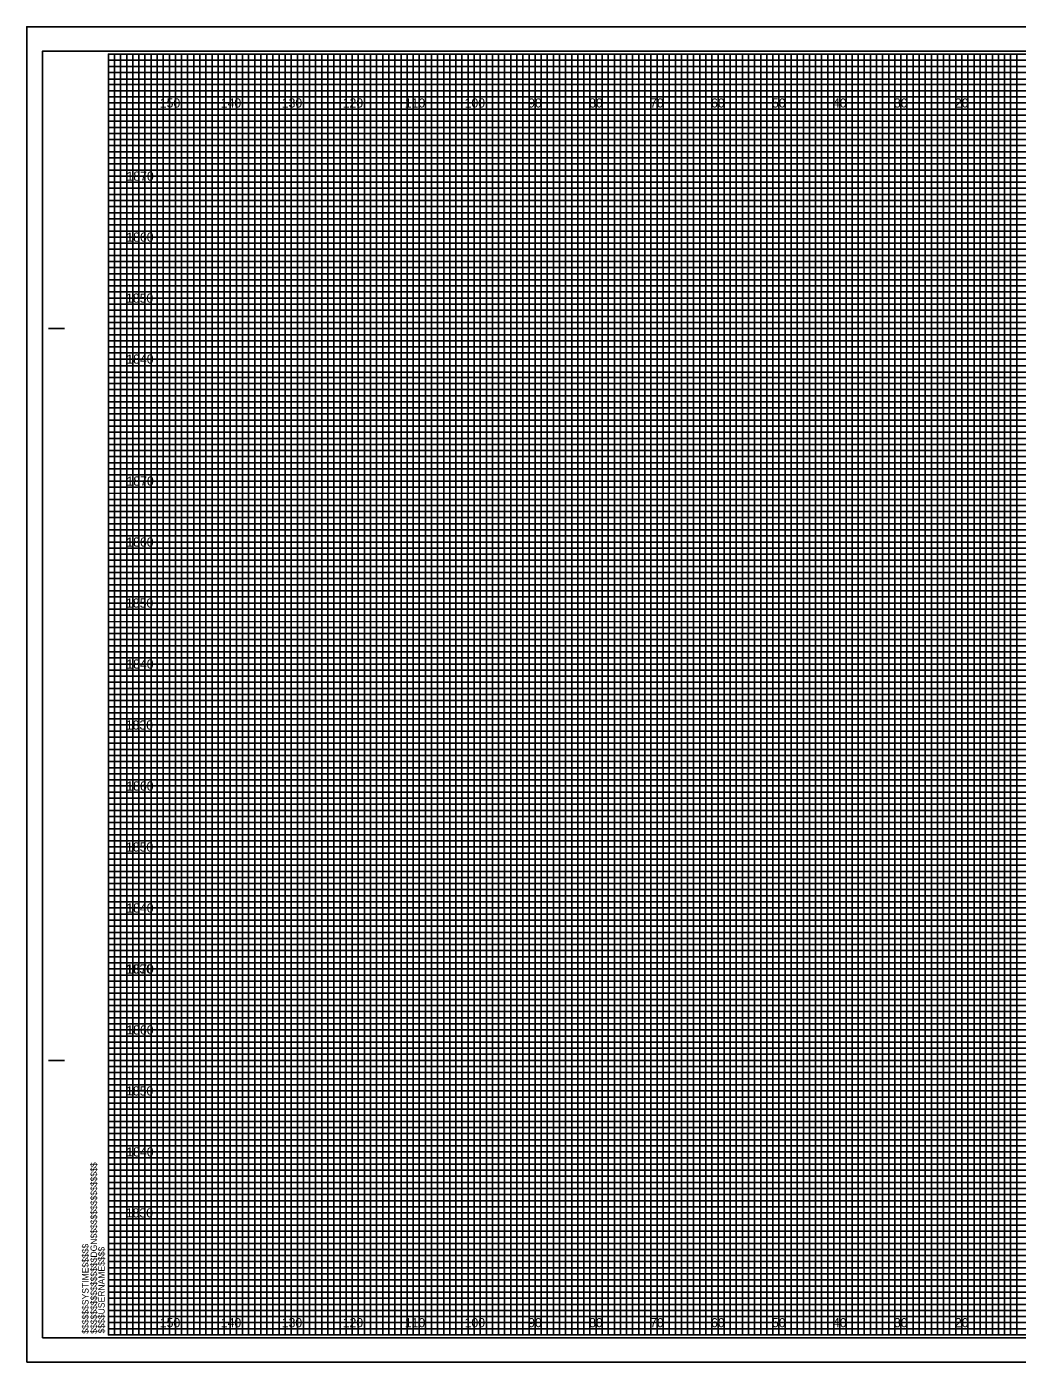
# Model space of a CAD drawing. Extents: x -13 to 323, y 8136 to 8354.
# Drawn here: x -13.4 to 149.1, y 8135.5 to 8354.5 of the extents above; entities that cross this region are included whole.
import ezdxf

# ---------------------------------------------------------------- set-up
doc = ezdxf.new("R2010")
doc.units = 0
for name, color, linetype in [('Prop XS Elevation Labels', 7, 'Continuous'), ('Prop XS Offset Labels', 7, 'Continuous'), ('Sheet Cross Section CELL', 7, 'Continuous'), ('Sheet Cross Section Grid Major CELL', 7, 'Continuous'), ('Sheet Cross Section Grid Middle CELL', 7, 'Continuous'), ('Sheet Cross Section Grid Minor 1 CELL', 7, 'Continuous'), ('Sheet Cross Section Grid Minor 2 CELL', 7, 'Continuous'), ('Sheet Cutting Line CELL', 7, 'Continuous'), ('Sheet DOT Grid CELL', 7, 'Continuous'), ('Sheet Plot Border Inside CELL', 7, 'Continuous'), ('Sheet Plot Border Outside CELL', 7, 'Continuous')]:
    doc.layers.add(name, color=color, linetype=linetype)

msp = doc.modelspace()

# ---------------------------------------------------------------- linework, layer by layer
at = {"layer": 'Sheet Cross Section CELL'}
for p, q in [((-9.8, 8305), (-7.3, 8305)), ((-9.7, 8305), (-7.2, 8305)), ((-9.8, 8185), (-7.3, 8185)), ((-9.7, 8185), (-7.2, 8185))]:
    msp.add_line(p, q, dxfattribs=at)
msp.add_lwpolyline([(320, 8350), (0, 8350), (0, 8140), (320, 8140)], close=True, dxfattribs=at)
at = {"layer": 'Sheet Cross Section Grid Major CELL'}
for p, q in [((10, 8350), (0, 8350)), ((10, 8140), (10, 8350)), ((30, 8350), (20, 8350)), ((20, 8350), (20, 8140)), ((30, 8140), (30, 8350)), ((50, 8350), (40, 8350)), ((40, 8350), (40, 8140)), ((50, 8140), (50, 8350)), ((70, 8350), (60, 8350)), ((60, 8350), (60, 8140)), ((70, 8140), (70, 8350)), ((90, 8350), (80, 8350)), ((80, 8350), (80, 8140)), ((90, 8140), (90, 8350)), ((110, 8350), (100, 8350)), ((100, 8350), (100, 8140)), ((110, 8140), (110, 8350)), ((130, 8350), (120, 8350)), ((120, 8350), (120, 8140)), ((130, 8140), (130, 8350)), ((150, 8350), (140, 8350)), ((140, 8350), (140, 8140)), ((20, 8140), (10, 8140)), ((40, 8140), (30, 8140)), ((60, 8140), (50, 8140)), ((80, 8140), (70, 8140)), ((100, 8140), (90, 8140)), ((120, 8140), (110, 8140)), ((140, 8140), (130, 8140))]:
    msp.add_line(p, q, dxfattribs=at)
for points in [[(0, 8340), (320, 8340), (320, 8330), (0, 8330)], [(0, 8320), (320, 8320), (320, 8310), (0, 8310)], [(0, 8300), (320, 8300), (320, 8290), (0, 8290)], [(0, 8280), (320, 8280), (320, 8270), (0, 8270)], [(0, 8260), (320, 8260), (320, 8250), (0, 8250)], [(0, 8240), (320, 8240), (320, 8230), (0, 8230)], [(0, 8220), (320, 8220), (320, 8210), (0, 8210)], [(0, 8200), (320, 8200), (320, 8190), (0, 8190)], [(0, 8180), (320, 8180), (320, 8170), (0, 8170)], [(0, 8160), (320, 8160), (320, 8150), (0, 8150)]]:
    msp.add_lwpolyline(points, dxfattribs=at)
at = {"layer": 'Sheet Cross Section Grid Middle CELL'}
for points in [[(0, 8350), (5, 8350), (5, 8140), (15, 8140), (15, 8350), (25, 8350), (25, 8140), (35, 8140), (35, 8350), (45, 8350), (45, 8140), (55, 8140), (55, 8350), (65, 8350), (65, 8140), (75, 8140), (75, 8350), (85, 8350), (85, 8140), (95, 8140), (95, 8350), (105, 8350), (105, 8140), (115, 8140), (115, 8350), (125, 8350), (125, 8140), (135, 8140), (135, 8350), (145, 8350), (145, 8140), (155, 8140)], [(0, 8345), (275, 8345)], [(0, 8325), (320, 8325), (320, 8335), (0, 8335)], [(0, 8305), (320, 8305), (320, 8315), (0, 8315)], [(0, 8285), (320, 8285), (320, 8295), (0, 8295)], [(0, 8265), (320, 8265), (320, 8275), (0, 8275)], [(0, 8245), (320, 8245), (320, 8255), (0, 8255)], [(0, 8225), (320, 8225), (320, 8235), (0, 8235)], [(0, 8205), (320, 8205), (320, 8215), (0, 8215)], [(0, 8185), (320, 8185), (320, 8195), (0, 8195)], [(0, 8165), (320, 8165), (320, 8175), (0, 8175)], [(0, 8145), (320, 8145), (320, 8155), (0, 8155)]]:
    msp.add_lwpolyline(points, dxfattribs=at)
at = {"layer": 'Sheet Cross Section Grid Minor 1 CELL'}
for p, q in [((0, 8349), (260, 8349)), ((260, 8347.98), (0, 8347.98)), ((0, 8347.98), (0, 8347)), ((0, 8347), (260, 8347)), ((260, 8345.89), (0, 8345.89)), ((0, 8345.89), (0, 8344)), ((0, 8344), (320, 8344))]:
    msp.add_line(p, q, dxfattribs=at)
for points in [[(0, 8343), (270, 8343), (320, 8343), (320, 8342), (0, 8342)], [(0, 8341), (320, 8341), (320, 8339), (0, 8339)], [(0, 8338), (320, 8338), (320, 8337), (0, 8336.98)], [(0, 8336), (320, 8336), (320, 8334), (0, 8334)], [(0, 8333), (320, 8333), (320, 8332), (0, 8332)], [(0, 8331), (320, 8331), (320, 8329), (0, 8329)], [(0, 8328), (320, 8328), (320, 8327), (0, 8327)], [(0, 8326), (320, 8326), (320, 8324), (0, 8324)], [(0, 8323), (320, 8323), (320, 8322), (0, 8322)], [(0, 8321), (320, 8321), (320, 8319), (0, 8319)], [(0, 8318), (320, 8318), (320, 8317), (0, 8317)], [(0, 8316), (320, 8316), (320, 8313.95), (320, 8313), (320, 8312), (0, 8312)], [(0, 8314), (320, 8314), (320, 8313), (0, 8313)], [(0, 8311), (320, 8311), (320, 8309), (0, 8309.03)], [(0, 8309.03), (320, 8309), (320, 8308), (0, 8308)], [(0, 8307), (320, 8307), (320, 8306), (0, 8306)], [(0, 8304), (320, 8304), (320, 8303), (0, 8303)], [(0, 8302), (320, 8302), (320, 8301), (0, 8301)], [(-0.07, 8298.89), (320, 8298.89), (320, 8297.88), (-0.07, 8297.88)], [(0, 8297), (320, 8297), (320, 8296), (0, 8296)], [(0, 8294), (320, 8294), (320, 8293), (0, 8293)], [(0, 8292), (320, 8292), (320, 8291), (0, 8291)], [(0, 8289), (320, 8289), (320, 8288), (0, 8288)], [(0, 8287), (320, 8287), (320, 8286), (0, 8286)], [(0, 8284), (320, 8284), (320, 8283), (0, 8283)], [(0, 8282), (320, 8282), (320, 8281), (0, 8281)], [(0, 8279), (320, 8279), (319.99, 8277.98), (0, 8278)], [(0, 8277), (320, 8277), (320, 8276), (0, 8276)], [(0, 8274), (320, 8274), (320, 8273), (0, 8273)], [(0, 8272), (320, 8272), (320, 8271), (0, 8271)], [(0, 8269), (320, 8269), (320, 8268), (0, 8268)], [(0, 8267), (320, 8267), (320, 8266), (0, 8266)], [(0, 8264), (320, 8264), (320, 8263), (0, 8263)], [(0, 8262), (320, 8262), (320, 8261), (0, 8261)], [(0, 8259), (320, 8259), (320, 8258), (0, 8258)], [(0, 8256.99), (320.07, 8256.91), (320, 8256), (0, 8256)], [(0, 8254), (320, 8254), (320, 8253), (0, 8253)], [(0, 8252), (320, 8252), (320, 8251), (0, 8251)], [(0, 8249), (320, 8249), (320, 8248), (0, 8248)], [(0, 8247), (320, 8247), (320, 8246), (0, 8246)], [(0, 8244), (320, 8244), (320, 8243), (0, 8243)], [(0, 8242), (320, 8242), (320, 8241), (0, 8241)], [(0, 8239), (320, 8239), (320, 8238), (0, 8238)], [(0, 8237), (320, 8237), (320, 8236), (0, 8236)], [(0, 8234), (320, 8234), (320, 8233), (0, 8233)], [(0, 8232), (320, 8232), (320, 8231), (0, 8231)], [(0, 8229), (320, 8229), (320, 8228), (0, 8228)], [(0, 8227), (320, 8227), (320, 8226), (0, 8226)], [(0, 8224), (320, 8224), (320, 8223), (0, 8223)], [(0, 8222), (320, 8222), (320, 8221), (0, 8221)], [(0, 8219), (320, 8219), (319.99, 8217.98), (0, 8218)], [(0, 8217), (320, 8217), (320, 8216), (0, 8216)], [(0, 8214), (320, 8214), (320, 8213), (0, 8213)], [(0, 8212), (320, 8212), (320, 8211), (0, 8211)], [(0, 8209), (320, 8209), (320, 8208), (0, 8208)], [(0, 8207), (320, 8207), (320, 8206), (0, 8206)], [(0, 8204), (320, 8204), (320, 8203), (0, 8203)], [(0, 8202), (320, 8202), (320, 8201), (0, 8201)], [(0, 8199), (320, 8199), (320, 8198), (0, 8198)], [(0, 8196.99), (320.07, 8196.91), (320, 8196), (0, 8196)], [(0, 8194), (320, 8194), (320, 8193), (0, 8193)], [(0, 8192), (320, 8192), (320, 8191), (0, 8191)], [(0, 8189), (320, 8189), (320, 8188), (0, 8188)], [(0, 8187), (320, 8187), (320, 8186), (0, 8186)], [(0, 8184), (320, 8184), (320, 8183), (0, 8183)], [(0, 8182), (320, 8182), (320, 8181), (0, 8181)], [(0, 8179), (320, 8179), (320, 8178), (0, 8178)], [(0, 8177), (320, 8177), (320, 8176), (0, 8176)], [(0, 8174), (320, 8174), (320, 8173), (0, 8173)], [(0, 8172), (320, 8172), (320, 8171), (0, 8171)], [(0, 8169), (320, 8169), (320, 8168), (0, 8168)], [(0, 8167), (320, 8167), (320, 8166), (0, 8166)], [(0, 8164), (320, 8164), (320, 8163), (0, 8163)], [(0, 8162), (320, 8162), (320, 8161), (0, 8161)], [(0, 8159), (320, 8159), (320, 8158), (0, 8158)], [(0, 8157), (320, 8157), (320, 8156), (0, 8156)], [(0, 8154), (320, 8154), (320, 8153), (0, 8153)], [(0, 8152), (320, 8152), (320, 8151), (0, 8151)], [(0, 8149), (320, 8149), (320, 8148), (0, 8148)], [(0, 8147), (320, 8147), (320, 8146), (0, 8146)], [(0, 8144), (320, 8144), (320, 8143), (0, 8143)], [(0, 8142), (320, 8142), (320, 8141), (0, 8141)]]:
    msp.add_lwpolyline(points, dxfattribs=at)
at = {"layer": 'Sheet Cross Section Grid Minor 2 CELL'}
for points in [[(0, 8140), (1, 8140), (1, 8350), (2, 8350), (2, 8140)], [(2, 8140), (3, 8140), (3, 8350), (4, 8350), (4, 8140)], [(5, 8140), (6, 8140), (6, 8350), (7, 8350), (7, 8140)], [(7, 8140), (8, 8140), (8, 8350), (9, 8350), (9, 8140)], [(10, 8140), (11, 8140), (11, 8350), (12, 8350), (12, 8140)], [(12, 8140), (13, 8140), (13, 8350), (14, 8350), (14, 8140)], [(15, 8140), (16, 8140), (16, 8350), (17, 8350), (17, 8140)], [(17, 8140), (18, 8140), (18, 8350), (19, 8350), (19, 8140)], [(20, 8140), (21, 8140), (21, 8350), (22, 8350), (22, 8140)], [(22, 8140), (23, 8140), (23, 8350), (24, 8350), (24, 8140)], [(25, 8140), (26, 8140), (26, 8350), (27, 8350), (27, 8140)], [(27, 8140), (28, 8140), (28, 8350), (29, 8350), (29, 8140)], [(30, 8140), (31, 8140), (31, 8350), (32, 8350), (32, 8140)], [(32, 8140), (33, 8140), (33, 8350), (34, 8350), (34, 8140)], [(35, 8140), (36, 8140), (36, 8350), (37, 8350), (37, 8140)], [(37, 8140), (38, 8140), (38, 8350), (39, 8350), (39, 8140)], [(40, 8140), (41, 8140), (41, 8350), (42, 8350), (42, 8140)], [(42, 8140), (43, 8140), (43, 8350), (44, 8350), (44, 8140)], [(45, 8140), (46, 8140), (46, 8350), (47, 8350), (47, 8140)], [(47, 8140), (48, 8140), (48, 8350), (49, 8350), (49, 8140)], [(50, 8140), (51, 8140), (51, 8350), (52, 8350), (52, 8140)], [(52, 8140), (53, 8140), (53, 8350), (54, 8350), (54, 8140)], [(55, 8140), (56, 8140), (56, 8350), (57, 8350), (57, 8140)], [(57, 8140), (58, 8140), (58, 8350), (59, 8350), (59, 8140)], [(60, 8140), (61, 8140), (61, 8350), (62, 8350), (62, 8140)], [(62, 8140), (63, 8140), (63, 8350), (64, 8350), (64, 8140)], [(65, 8140), (66, 8140), (66, 8350), (67, 8350), (67, 8140)], [(67, 8140), (68, 8140), (68, 8350), (69, 8350), (69, 8140)], [(70, 8140), (71, 8140), (71, 8350), (72, 8350), (72, 8140)], [(72, 8140), (73, 8140), (73, 8350), (74, 8350), (74, 8140)], [(75, 8140), (76, 8140), (76, 8350), (77, 8350), (77, 8140)], [(77, 8140), (78, 8140), (78, 8350), (79, 8350), (79, 8140)], [(80, 8140), (81, 8140), (81, 8350), (82, 8350), (82, 8140)], [(82, 8140), (83, 8140), (83, 8350), (84, 8350), (84, 8140)], [(85, 8140), (86, 8140), (86, 8350), (87, 8350), (87, 8140)], [(87, 8140), (88, 8140), (88, 8350), (89, 8350), (89, 8140)], [(90, 8140), (91, 8140), (91, 8350), (92, 8350), (92, 8140)], [(92, 8140), (93, 8140), (93, 8350), (94, 8350), (94, 8140)], [(95, 8140), (96, 8140), (96, 8350), (97, 8350), (97, 8140)], [(97, 8140), (98, 8140), (98, 8350), (99, 8350), (99, 8140)], [(100, 8140), (101, 8140), (101, 8350), (102, 8350), (102, 8140)], [(102, 8140), (103, 8140), (103, 8350), (104, 8350), (104, 8140)], [(105, 8140), (106, 8140), (106, 8350), (107, 8350), (107, 8140)], [(107, 8140), (108, 8140), (108, 8350), (109, 8350), (109, 8140)], [(110, 8140), (111, 8140), (111, 8350), (112, 8350), (112, 8140)], [(112, 8140), (113, 8140), (113, 8350), (114, 8350), (114, 8140)], [(115, 8140), (116, 8140), (116, 8350), (117, 8350), (117, 8140)], [(117, 8140), (118, 8140), (118, 8350), (119, 8350), (119, 8140)], [(120, 8140), (121, 8140), (121, 8350), (122, 8350), (122, 8140)], [(122, 8140), (123, 8140), (123, 8350), (124, 8350), (124, 8140)], [(125, 8140), (126, 8140), (126, 8350), (127, 8350), (127, 8140)], [(127, 8140), (128, 8140), (128, 8350), (129, 8350), (129, 8140)], [(130, 8140), (131, 8140), (131, 8350), (132, 8350), (132, 8140)], [(132, 8140), (133, 8140), (133, 8350), (134, 8350), (134, 8140)], [(135, 8140), (136, 8140), (136, 8350), (137, 8350), (137, 8140)], [(137, 8140), (138, 8140), (138, 8350), (139, 8350), (139, 8140)], [(140, 8140), (141, 8140), (141, 8350), (142, 8350), (142, 8140)], [(142, 8140), (143, 8140), (143, 8350), (144, 8350), (144, 8140)], [(145, 8140), (146, 8140), (146, 8350), (147, 8350), (147, 8140)], [(147, 8140), (148, 8140), (148, 8350), (149, 8350), (149, 8140)]]:
    msp.add_lwpolyline(points, dxfattribs=at)
at = {"layer": 'Sheet Cutting Line CELL'}
for p, q in [((323.3, 8354.5), (-13.4, 8354.5)), ((-13.4, 8354.5), (-13.4, 8135.5)), ((-13.4, 8135.5), (323.3, 8135.5))]:
    msp.add_line(p, q, dxfattribs=at)
at = {"layer": 'Sheet DOT Grid CELL'}
for p, q in [((10, 8140), (10, 8350)), ((20, 8140), (20, 8350)), ((30, 8140), (30, 8350)), ((40, 8140), (40, 8350)), ((50, 8140), (50, 8350)), ((60, 8140), (60, 8350)), ((70, 8140), (70, 8350)), ((80, 8140), (80, 8350)), ((90, 8140), (90, 8350)), ((100, 8140), (100, 8350)), ((110, 8140), (110, 8350)), ((120, 8140), (120, 8350)), ((130, 8140), (130, 8350)), ((140, 8140), (140, 8350)), ((0, 8340), (320, 8340)), ((0, 8330), (320, 8330)), ((0, 8320), (320, 8320)), ((0, 8310), (320, 8310)), ((0, 8300), (320, 8300)), ((0, 8290), (320, 8290)), ((0, 8280), (320, 8280)), ((0, 8270), (320, 8270)), ((0, 8260), (320, 8260)), ((0, 8250), (320, 8250)), ((0, 8240), (320, 8240)), ((0, 8230), (320, 8230)), ((0, 8220), (320, 8220)), ((0, 8210), (320, 8210)), ((0, 8200), (320, 8200)), ((0, 8190), (320, 8190)), ((0, 8180), (320, 8180)), ((0, 8170), (320, 8170)), ((0, 8160), (320, 8160)), ((0, 8150), (320, 8150))]:
    msp.add_line(p, q, dxfattribs=at)
at = {"layer": 'Sheet Plot Border Inside CELL'}
msp.add_lwpolyline([(-10.8, 8139.5), (322.4, 8139.5), (322.4, 8350.5), (-10.8, 8350.5)], close=True, dxfattribs=at)
at = {"layer": 'Sheet Plot Border Outside CELL'}
msp.add_lwpolyline([(-13.4, 8135.5), (323.3, 8135.5), (323.3, 8354.5), (-13.4, 8354.5)], close=True, dxfattribs=at)

# ---------------------------------------------------------------- texts
at = {"layer": 'Prop XS Elevation Labels'}
for s, p in [('1870', (2.98, 8329.25)), ('1860', (2.95, 8319.25)), ('1850', (2.9, 8309.25)), ('1840', (2.95, 8299.25)), ('1870', (2.98, 8279.25)), ('1860', (2.95, 8269.25)), ('1850', (2.9, 8259.25)), ('1840', (2.95, 8249.25)), ('1830', (2.86, 8239.25)), ('1860', (2.95, 8229.25)), ('1850', (2.9, 8219.25)), ('1840', (2.95, 8209.25)), ('1830', (2.86, 8199.25)), ('1870', (2.98, 8199.25)), ('1860', (2.95, 8189.25)), ('1850', (2.9, 8179.25)), ('1840', (2.95, 8169.25)), ('1830', (2.86, 8159.25))]:
    msp.add_text(s, height=1.5, dxfattribs=at).set_placement(p)
at = {"layer": 'Prop XS Offset Labels'}
for s, p in [('150', (8.44, 8341.25)), ('140', (18.44, 8341.25)), ('130', (28.44, 8341.25)), ('120', (38.44, 8341.25)), ('110', (48.62, 8341.25)), ('100', (58.44, 8341.25)), ('90', (68.86, 8341.25)), ('80', (78.86, 8341.25)), ('70', (88.86, 8341.25)), ('60', (98.86, 8341.25)), ('50', (108.86, 8341.25)), ('40', (118.86, 8341.25)), ('30', (128.86, 8341.25)), ('20', (138.86, 8341.25)), ('150', (8.44, 8141.25)), ('140', (18.44, 8141.25)), ('130', (28.44, 8141.25)), ('120', (38.44, 8141.25)), ('110', (48.62, 8141.25)), ('100', (58.44, 8141.25)), ('90', (68.86, 8141.25)), ('80', (78.86, 8141.25)), ('70', (88.86, 8141.25)), ('60', (98.86, 8141.25)), ('50', (108.86, 8141.25)), ('40', (118.86, 8141.25)), ('30', (128.86, 8141.25)), ('20', (138.86, 8141.25))]:
    msp.add_text(s, height=1.5, dxfattribs=at).set_placement(p)
at = {"layer": 'Sheet Cross Section CELL'}
for s, p in [('$$$$$$$$$$$$$$$$DGN$$$$$$$$$$$$$$$$', (-1.88, 8140.18)), ('$$$$$$SYSTIME$$$$$', (-3.26, 8140.18)), ('$$$$USERNAME$$$$', (-0.62, 8140.23))]:
    msp.add_text(s, height=1.05, rotation=90, dxfattribs=at).set_placement(p)

doc.saveas('drawing.dxf')
